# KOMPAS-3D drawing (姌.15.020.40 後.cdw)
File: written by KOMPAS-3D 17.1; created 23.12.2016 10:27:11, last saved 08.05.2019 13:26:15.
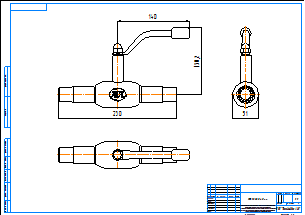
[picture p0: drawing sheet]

Sheet 1: A2, landscape

Title block, sheet 1: name: КШ.15.020.40 сс; material: Внимание! Данный продукт является объектом авторского права ООО «Торговый Дом АДЛ». / Запрещается изменение, копирование, распространение / (в том числе путем копирования на другие сайты и ресурсы в Интернете) / или любое иное использование информации и объектов без предварительного / согласия правообладателя (ООО «Торговый Дом АДЛ»).; sheets: 1; organisation: ООО "Торговый дом АДЛ"; sheet format: A2; stored path: C:\Users\tra\Desktop\2д чертежи\Шаровые краны БИВАЛ\КШ_Бивал_серия_14_15\KOMPAS_2D\КШ.15.020.40 сс.cdw

Views: Вид 1, Проекционный вид 2, Проекционный вид 3
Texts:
  Klimkovich
  ADL
Dimensions and other numbers on the sheet: 230; 140; 130,2; 51; 1:1; 1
